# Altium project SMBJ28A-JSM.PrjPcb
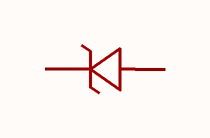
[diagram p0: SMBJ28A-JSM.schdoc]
1 sheet, 1 parts. Net scope: global (net labels, ports and power ports of the same name join across sheets).

## Sheet SMBJ28A-JSM.schdoc
size 127 x 101 mm

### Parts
D?  smbj28a-jsm  [SMB_L4.4-W3.6-LS5.3-RD]  (value not drawn)

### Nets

Not connected (* = marked no-connect by the designer): D? 1(K) 2(A)

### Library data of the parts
D? = smbj28a-jsm: 极性:单向;反向截止电压(Vrwm):28V;钳位电压:45.4V;峰值脉冲电流(Ipp):13.3A;峰值脉冲功率(Ppp):600W;击穿电压(VBR):34.4V;; Manufacturer: JSMSEMI(杰盛微); AddInBom: yes; ModelId: 2e2b5067ebdf4b2391651ce058af3163; ModelTransform: 208.661,142.5194,0,0,0,0,0,0,0; Polarity: 单向; Reverse Stand-Off Voltage (Vrwm): 28V; Clamping Voltage: 45.4V; Peak Pulse Current (Ipp): 13.3A; Peak Pulse Power Dissipation (Ppp): 600W; Voltage - Breakdown: 34.4V; Reverse Leakage Current (Ir): 1uA; Number of Channels: 单路; Type: TVS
